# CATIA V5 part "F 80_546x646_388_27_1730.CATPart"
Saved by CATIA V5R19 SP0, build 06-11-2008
Definition: F 80_546x646_388_27_1730
Nomenclature: F 80_546x646_388_27_1730
Description: PART--DESC
Material "Steel": density 7860 kg/m3, Young's modulus 2e+11 Pa, Poisson ratio 0.266, thermal expansion 1.17e-05 1/K
Bounding box of the stored display mesh (mm): x -323 to 323, y -194 to 194, z -238 to -211
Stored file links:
  G:\UTB\Kombinované\Bakalářská práce\Catia\FORMA\F 80_546x646_388_27_1730.CATPart
  D:\Aplikace\CATIA\Nová složka\win_b64\startup\materials\Catalog.CATMaterial
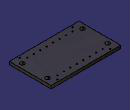
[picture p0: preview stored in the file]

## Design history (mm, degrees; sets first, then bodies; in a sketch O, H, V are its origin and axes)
Body1 "F 80_546646_388_27_1730" (main body)
  Solid1: solid without history
  Sketch1 on face of Solid1, origin (-217.2275, -110.4955, -238), H (1, 0, 0), V (0, -1, 0)
    point P1 (7.2275, 29.5045)
    reference intersected line E1 through (0, -110.4955) direction (1, 0) from zx-plane
    reference intersected line E2 through (217.2275, 0) direction (0, 1) from yz-plane
    distance P1 E1 = 140
    distance P1 E2 = 210
  Hole1: placed by Sketch1, at (-210, -140, -238) direction (0, 0, 1), diameter 12, through (limit type 6), counterbore diameter 20, counterbore depth 7
  Chamfer1: length 1, angle 45, on edge [face of Hole1 | face of Hole1]; edge [face of Hole1 | face of Solid1]
  RectPattern1: of Hole1, Chamfer1, direction 1 instances 8, spacing 60, along X axis, direction 2 instances 2, spacing 280, along Y axis
  Sketch2 on face of Solid1, origin (-258.3863, -83.3732, -238), H (1, 0, 0), V (0, -1, 0)
    point P1 (-20.6137, 34.1268)
    reference intersected line E1 through (0, -83.3732) direction (1, 0) from Plane1
    reference intersected line E2 through (258.3863, 0) direction (0, 1) from Plane2
    distance P1 E1 = 117.5
    distance P1 E2 = 279
  Hole2: placed by Sketch2, at (-279, -117.5, -238) direction (0, 0, 1), diameter 38, through (limit type 6)
  RectPattern2: of Hole2, direction 1 instances 2, spacing 558, along X axis, direction 2 instances 2, spacing 235, along Y axis
  Plane1: stored without definition
  Plane2: stored without definition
